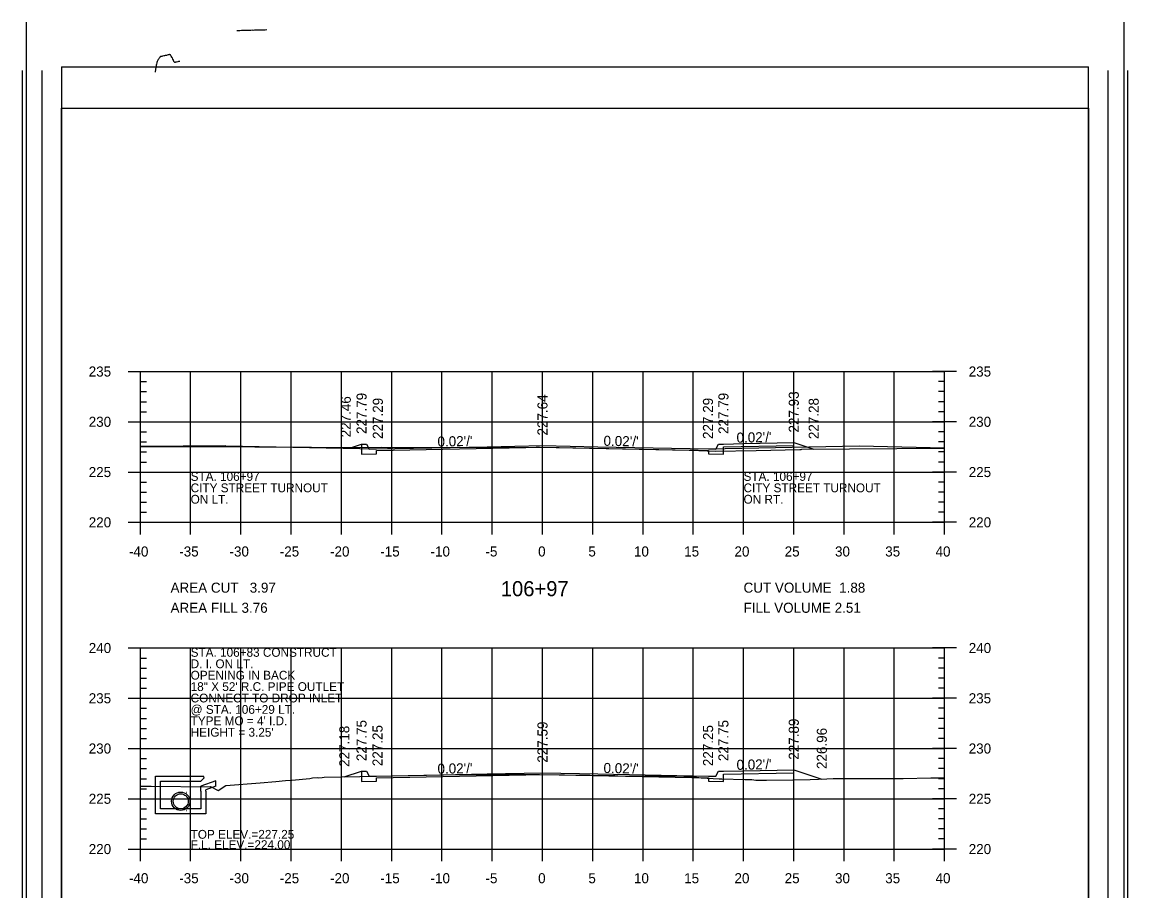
# Model space of a CAD drawing. Extents: x 1367903 to 1373764, y 376865 to 382130.
# Drawn here: x 1371403 to 1371623, y 377447.5 to 377620.4 of the extents above; entities that cross this region are included whole.
import ezdxf

# ---------------------------------------------------------------- set-up
doc = ezdxf.new("R2010")
doc.units = 0
for name, color, linetype in [('R_Axis', 7, 'Continuous'), ('R_Axis Annot', 7, 'Continuous'), ('R_Border', 7, 'Continuous'), ('R_Border PE', 7, 'Continuous'), ('R_Draft', 7, 'Continuous'), ('R_Drive', 7, 'Continuous'), ('R_Exist Surface', 7, 'Continuous'), ('R_Fin Surface', 7, 'Continuous'), ('R_Fin Surface Annot', 7, 'Continuous'), ('R_Grid', 7, 'Continuous'), ('R_Water', 7, 'Continuous'), ('R_Water Annot', 7, 'Continuous')]:
    doc.layers.add(name, color=color, linetype=linetype)

msp = doc.modelspace()

# ---------------------------------------------------------------- linework, layer by layer
for p, q in [((1371429.54, 377470.34), (1371439.04, 377470.34)), ((1371429.54, 377467.34), (1371429.54, 377470.34)), ((1371439.21, 377470), (1371438.54, 377469.34)), ((1371439.21, 377470), (1371439.04, 377470.34)), ((1371430.54, 377467.34), (1371430.54, 377469.34)), ((1371430.54, 377469.34), (1371438.54, 377469.34)), ((1371441.54, 377469.38), (1371438.54, 377468.34)), ((1371438.54, 377467.34), (1371438.54, 377468.34)), ((1371441.54, 377468.32), (1371439.54, 377467.62)), ((1371439.54, 377467.34), (1371439.54, 377467.62))]:
    msp.add_line(p, q)
for points in [[(1371470.51, 377536.42), (1371470.51, 377535.76), (1371470.51, 377535.76), (1371470.51, 377534.39), (1371473.51, 377534.45), (1371473.51, 377535.12), (1371506.51, 377535.78), (1371539.51, 377535.12), (1371539.51, 377534.45), (1371542.51, 377534.39), (1371542.51, 377535.84), (1371556.51, 377536.12), (1371556.51, 377536.7)], [(1371470.51, 377471.33), (1371470.51, 377470.67), (1371470.51, 377470.67), (1371470.51, 377469.3), (1371473.51, 377469.36), (1371473.51, 377470.03), (1371506.51, 377470.69), (1371539.51, 377470.03), (1371539.51, 377469.36), (1371542.51, 377469.3), (1371542.51, 377470.75), (1371556.51, 377471.03), (1371556.51, 377471.61)], [(1371441.54, 377468.32), (1371441.54, 377469.38)]]:
    msp.add_lwpolyline(points)
at = {"layer": 'R_Axis'}
for p, q in [((1371424.11, 377550.84), (1371428.91, 377550.84)), ((1371426.51, 377520.84), (1371426.51, 377550.84)), ((1371588.91, 377550.84), (1371584.11, 377550.84)), ((1371586.51, 377520.84), (1371586.51, 377550.84)), ((1371426.51, 377548.84), (1371427.71, 377548.84)), ((1371586.51, 377548.84), (1371585.31, 377548.84)), ((1371426.51, 377546.84), (1371427.71, 377546.84)), ((1371426.51, 377544.84), (1371427.71, 377544.84)), ((1371586.51, 377546.84), (1371585.31, 377546.84)), ((1371586.51, 377544.84), (1371585.31, 377544.84)), ((1371426.51, 377542.84), (1371427.71, 377542.84)), ((1371586.51, 377542.84), (1371585.31, 377542.84)), ((1371424.11, 377540.84), (1371428.91, 377540.84)), ((1371588.91, 377540.84), (1371584.11, 377540.84)), ((1371426.51, 377538.84), (1371427.71, 377538.84)), ((1371586.51, 377538.84), (1371585.31, 377538.84)), ((1371426.51, 377536.84), (1371427.71, 377536.84)), ((1371586.51, 377536.84), (1371585.31, 377536.84)), ((1371426.51, 377534.84), (1371427.71, 377534.84)), ((1371586.51, 377534.84), (1371585.31, 377534.84)), ((1371426.51, 377532.84), (1371427.71, 377532.84)), ((1371586.51, 377532.84), (1371585.31, 377532.84)), ((1371424.11, 377530.84), (1371428.91, 377530.84)), ((1371588.91, 377530.84), (1371584.11, 377530.84)), ((1371426.51, 377528.84), (1371427.71, 377528.84)), ((1371586.51, 377528.84), (1371585.31, 377528.84)), ((1371426.51, 377526.84), (1371427.71, 377526.84)), ((1371586.51, 377526.84), (1371585.31, 377526.84)), ((1371426.51, 377524.84), (1371427.71, 377524.84)), ((1371426.51, 377518.44), (1371426.51, 377523.24)), ((1371426.51, 377522.84), (1371427.71, 377522.84)), ((1371436.51, 377518.44), (1371436.51, 377523.24)), ((1371446.51, 377518.44), (1371446.51, 377523.24)), ((1371456.51, 377518.44), (1371456.51, 377523.24)), ((1371466.51, 377518.44), (1371466.51, 377523.24)), ((1371476.51, 377518.44), (1371476.51, 377523.24)), ((1371486.51, 377518.44), (1371486.51, 377523.24)), ((1371496.51, 377518.44), (1371496.51, 377523.24)), ((1371506.51, 377518.44), (1371506.51, 377523.24)), ((1371516.51, 377518.44), (1371516.51, 377523.24)), ((1371526.51, 377518.44), (1371526.51, 377523.24)), ((1371536.51, 377518.44), (1371536.51, 377523.24)), ((1371546.51, 377518.44), (1371546.51, 377523.24)), ((1371556.51, 377518.44), (1371556.51, 377523.24)), ((1371566.51, 377518.44), (1371566.51, 377523.24)), ((1371576.51, 377518.44), (1371576.51, 377523.24)), ((1371586.51, 377524.84), (1371585.31, 377524.84)), ((1371586.51, 377522.84), (1371585.31, 377522.84)), ((1371586.51, 377518.44), (1371586.51, 377523.24)), ((1371424.11, 377520.84), (1371428.91, 377520.84)), ((1371426.51, 377520.84), (1371586.51, 377520.84)), ((1371588.91, 377520.84), (1371584.11, 377520.84)), ((1371424.11, 377495.84), (1371428.91, 377495.84)), ((1371426.51, 377455.84), (1371426.51, 377495.84)), ((1371588.91, 377495.84), (1371584.11, 377495.84)), ((1371586.51, 377455.84), (1371586.51, 377495.84)), ((1371426.51, 377493.84), (1371427.71, 377493.84)), ((1371586.51, 377493.84), (1371585.31, 377493.84)), ((1371426.51, 377491.84), (1371427.71, 377491.84)), ((1371426.51, 377489.84), (1371427.71, 377489.84)), ((1371586.51, 377491.84), (1371585.31, 377491.84)), ((1371586.51, 377489.84), (1371585.31, 377489.84)), ((1371426.51, 377487.84), (1371427.71, 377487.84)), ((1371586.51, 377487.84), (1371585.31, 377487.84)), ((1371424.11, 377485.84), (1371428.91, 377485.84)), ((1371588.91, 377485.84), (1371584.11, 377485.84)), ((1371426.51, 377483.84), (1371427.71, 377483.84)), ((1371586.51, 377483.84), (1371585.31, 377483.84)), ((1371426.51, 377481.84), (1371427.71, 377481.84)), ((1371586.51, 377481.84), (1371585.31, 377481.84)), ((1371426.51, 377479.84), (1371427.71, 377479.84)), ((1371586.51, 377479.84), (1371585.31, 377479.84)), ((1371426.51, 377477.84), (1371427.71, 377477.84)), ((1371586.51, 377477.84), (1371585.31, 377477.84)), ((1371424.11, 377475.84), (1371428.91, 377475.84)), ((1371588.91, 377475.84), (1371584.11, 377475.84)), ((1371426.51, 377473.84), (1371427.71, 377473.84)), ((1371586.51, 377473.84), (1371585.31, 377473.84)), ((1371426.51, 377471.84), (1371427.71, 377471.84)), ((1371586.51, 377471.84), (1371585.31, 377471.84)), ((1371426.51, 377469.84), (1371427.71, 377469.84)), ((1371426.51, 377467.84), (1371427.71, 377467.84)), ((1371586.51, 377469.84), (1371585.31, 377469.84)), ((1371586.51, 377467.84), (1371585.31, 377467.84)), ((1371424.11, 377465.84), (1371428.91, 377465.84)), ((1371588.91, 377465.84), (1371584.11, 377465.84)), ((1371426.51, 377463.84), (1371427.71, 377463.84)), ((1371586.51, 377463.84), (1371585.31, 377463.84)), ((1371426.51, 377461.84), (1371427.71, 377461.84)), ((1371586.51, 377461.84), (1371585.31, 377461.84)), ((1371426.51, 377459.84), (1371427.71, 377459.84)), ((1371586.51, 377459.84), (1371585.31, 377459.84)), ((1371426.51, 377453.44), (1371426.51, 377458.24)), ((1371426.51, 377457.84), (1371427.71, 377457.84)), ((1371436.51, 377453.44), (1371436.51, 377458.24)), ((1371446.51, 377453.44), (1371446.51, 377458.24)), ((1371456.51, 377453.44), (1371456.51, 377458.24)), ((1371466.51, 377453.44), (1371466.51, 377458.24)), ((1371476.51, 377453.44), (1371476.51, 377458.24)), ((1371486.51, 377453.44), (1371486.51, 377458.24)), ((1371496.51, 377453.44), (1371496.51, 377458.24)), ((1371506.51, 377453.44), (1371506.51, 377458.24)), ((1371516.51, 377453.44), (1371516.51, 377458.24)), ((1371526.51, 377453.44), (1371526.51, 377458.24)), ((1371536.51, 377453.44), (1371536.51, 377458.24)), ((1371546.51, 377453.44), (1371546.51, 377458.24)), ((1371556.51, 377453.44), (1371556.51, 377458.24)), ((1371566.51, 377453.44), (1371566.51, 377458.24)), ((1371576.51, 377453.44), (1371576.51, 377458.24)), ((1371586.51, 377457.84), (1371585.31, 377457.84)), ((1371586.51, 377453.44), (1371586.51, 377458.24)), ((1371424.11, 377455.84), (1371428.91, 377455.84)), ((1371426.51, 377455.84), (1371586.51, 377455.84)), ((1371588.91, 377455.84), (1371584.11, 377455.84))]:
    msp.add_line(p, q, dxfattribs=at)
at = {"layer": 'R_Border'}
for p, q in [((1371403.79, 377620.35), (1371403.79, 377279.12)), ((1371622.18, 377620.35), (1371622.18, 377279.12)), ((1371410.82, 377611.47), (1371615.14, 377611.47)), ((1371410.82, 377611.47), (1371410.82, 377280.59)), ((1371615.14, 377280.59), (1371615.14, 377611.47))]:
    msp.add_line(p, q, dxfattribs=at)
at = {"layer": 'R_Border PE'}
for p, q in [((1371402.98, 377610.76), (1371402.98, 377288.8)), ((1371406.9, 377610.76), (1371406.9, 377288.8)), ((1371619.06, 377288.8), (1371619.06, 377610.76)), ((1371622.98, 377288.8), (1371622.98, 377610.76)), ((1371410.82, 377603.25), (1371615.14, 377603.25)), ((1371410.82, 377288.8), (1371410.82, 377603.25)), ((1371615.14, 377603.25), (1371615.14, 377288.8))]:
    msp.add_line(p, q, dxfattribs=at)
for points in [[(1371447.67, 377618.69), (1371447.62, 377618.69), (1371447.34, 377618.68), (1371447.21, 377618.68), (1371447.14, 377618.67), (1371446.99, 377618.67), (1371446.63, 377618.66), (1371446.3, 377618.65), (1371445.67, 377618.63)], [(1371448.13, 377618.7), (1371447.67, 377618.69)], [(1371451.69, 377618.79), (1371451.34, 377618.78), (1371451.14, 377618.78), (1371450.98, 377618.77), (1371450.75, 377618.76), (1371450.6, 377618.76), (1371450.4, 377618.75), (1371450.15, 377618.75), (1371449.96, 377618.74), (1371449.68, 377618.73), (1371449.58, 377618.73), (1371449.53, 377618.73), (1371449.31, 377618.72), (1371449.21, 377618.72), (1371448.98, 377618.71), (1371448.9, 377618.72), (1371448.48, 377618.7), (1371448.24, 377618.7), (1371448.13, 377618.7)], [(1371434.37, 377612.54), (1371434.35, 377612.55), (1371434.33, 377612.55), (1371434.31, 377612.55), (1371434.29, 377612.55), (1371434.26, 377612.55), (1371434.24, 377612.55), (1371434.21, 377612.55), (1371434.07, 377612.51), (1371433.95, 377612.48), (1371433.68, 377612.41), (1371433.47, 377612.36), (1371433.44, 377612.35), (1371433.42, 377612.35), (1371433.4, 377612.34), (1371433.39, 377612.34), (1371433.38, 377612.35), (1371433.35, 377612.35), (1371433.33, 377612.36), (1371433.31, 377612.38), (1371433.29, 377612.39), (1371433.27, 377612.4), (1371433.25, 377612.42), (1371433.23, 377612.45), (1371433.22, 377612.47), (1371433.2, 377612.5), (1371433.18, 377612.55), (1371433.09, 377612.76), (1371432.98, 377613), (1371432.87, 377613.23), (1371432.86, 377613.26), (1371432.85, 377613.28), (1371432.81, 377613.34), (1371432.78, 377613.39), (1371432.66, 377613.57), (1371432.58, 377613.69), (1371432.55, 377613.74), (1371432.54, 377613.76), (1371432.52, 377613.78), (1371432.5, 377613.81), (1371432.48, 377613.83), (1371432.47, 377613.84), (1371432.45, 377613.85), (1371432.42, 377613.87), (1371432.41, 377613.87), (1371432.38, 377613.88), (1371432.35, 377613.88), (1371432.34, 377613.88), (1371432.3, 377613.88), (1371432.2, 377613.86), (1371432.03, 377613.82), (1371431.83, 377613.77), (1371431.69, 377613.74), (1371431.58, 377613.72), (1371431.44, 377613.69), (1371431.32, 377613.66), (1371431.15, 377613.63), (1371430.93, 377613.58), (1371430.88, 377613.57), (1371430.76, 377613.54), (1371430.64, 377613.52), (1371430.6, 377613.51), (1371430.57, 377613.5), (1371430.55, 377613.5), (1371430.54, 377613.49), (1371430.52, 377613.49), (1371430.5, 377613.47), (1371430.48, 377613.46), (1371430.46, 377613.44), (1371430.44, 377613.42), (1371430.41, 377613.39), (1371430.38, 377613.35), (1371430.35, 377613.31), (1371430.31, 377613.26), (1371430.25, 377613.16), (1371430.16, 377613.02), (1371430.08, 377612.89), (1371429.98, 377612.75), (1371429.93, 377612.67), (1371429.89, 377612.62), (1371429.86, 377612.55), (1371429.85, 377612.54), (1371429.84, 377612.52), (1371429.83, 377612.5), (1371429.82, 377612.48), (1371429.82, 377612.46), (1371429.81, 377612.44), (1371429.8, 377612.42), (1371429.8, 377612.39), (1371429.79, 377612.37), (1371429.79, 377612.35), (1371429.78, 377612.33), (1371429.77, 377612.24), (1371429.73, 377612), (1371429.68, 377611.76), (1371429.66, 377611.65), (1371429.58, 377611.18), (1371429.55, 377611.04), (1371429.51, 377610.84), (1371429.46, 377610.54), (1371429.43, 377610.39)]]:
    msp.add_lwpolyline(points, dxfattribs=at)
at = {"layer": 'R_Drive'}
for p, q in [((1371443.52, 377536.05), (1371426.51, 377535.91)), ((1371443.52, 377536.05), (1371473.51, 377535.45)), ((1371539.51, 377535.45), (1371569.51, 377536.05)), ((1371569.51, 377536.05), (1371586.51, 377535.63))]:
    msp.add_line(p, q, dxfattribs=at)
at = {"layer": 'R_Exist Surface'}
for points in [[(1371426.51, 377535.93), (1371433.1, 377535.94), (1371437.5, 377535.94), (1371437.96, 377535.95), (1371471.9, 377535.73), (1371474.41, 377535.76), (1371475.66, 377535.72), (1371475.7, 377535.71), (1371475.73, 377535.71), (1371476.68, 377535.73), (1371505.26, 377535.79), (1371505.54, 377535.79), (1371505.6, 377535.79), (1371505.94, 377535.78), (1371535.7, 377535.19), (1371537.44, 377535.18), (1371537.6, 377535.15), (1371540.85, 377534.98), (1371549, 377535.15), (1371557.7, 377535.36), (1371557.97, 377535.36), (1371558.14, 377535.37), (1371586.51, 377535.56)], [(1371426.51, 377468.34), (1371428.64, 377468.32), (1371440.39, 377468.24), (1371440.49, 377468.25), (1371441.98, 377467.51), (1371441.98, 377467.51), (1371443.48, 377468.47), (1371450.34, 377469.01), (1371453.45, 377469.3), (1371455.36, 377469.46), (1371456.64, 377469.53), (1371460.2, 377469.9), (1371460.73, 377470.02), (1371461.76, 377470.05), (1371462.01, 377470.01), (1371462.68, 377470.09), (1371463.08, 377470.11), (1371470.2, 377470.26), (1371472.92, 377470.32), (1371476.43, 377470.4), (1371476.7, 377470.4), (1371490.23, 377470.68), (1371490.42, 377470.68), (1371503.39, 377470.69), (1371503.98, 377470.68), (1371505.92, 377470.65), (1371505.93, 377470.65), (1371520.9, 377470.44), (1371521.52, 377470.43), (1371534.62, 377470.32), (1371536.23, 377470.27), (1371538.06, 377469.99), (1371541.65, 377469.84), (1371542.18, 377469.82), (1371546.79, 377469.68), (1371548.17, 377469.68), (1371548.96, 377469.56), (1371549.29, 377469.54), (1371551.09, 377469.57), (1371556.3, 377469.62), (1371559.76, 377469.65), (1371563.06, 377469.8), (1371564.34, 377469.88), (1371570.17, 377469.86), (1371578.25, 377469.89), (1371583.8, 377469.98), (1371586.51, 377470.01)]]:
    msp.add_lwpolyline(points, dxfattribs=at)
at = {"layer": 'R_Fin Surface'}
for points in [[(1371468.5, 377535.75), (1371470.51, 377536.42), (1371471.51, 377536.42), (1371472.01, 377535.42), (1371473.51, 377535.45), (1371495.51, 377535.89), (1371506.51, 377536.11), (1371517.51, 377535.89), (1371539.51, 377535.45), (1371541.01, 377535.42), (1371541.51, 377536.42), (1371542.51, 377536.42), (1371546.51, 377536.5), (1371556.51, 377536.7), (1371560.47, 377535.39)], [(1371467.08, 377470.19), (1371470.51, 377471.33), (1371471.51, 377471.33), (1371472.01, 377470.33), (1371473.51, 377470.36), (1371495.51, 377470.8), (1371506.51, 377471.02), (1371517.51, 377470.8), (1371539.51, 377470.36), (1371541.01, 377470.33), (1371541.51, 377471.33), (1371542.51, 377471.33), (1371546.51, 377471.41), (1371556.51, 377471.61), (1371562.08, 377469.76)]]:
    msp.add_lwpolyline(points, dxfattribs=at)
at = {"layer": 'R_Grid'}
for p, q in [((1371426.51, 377550.84), (1371586.51, 377550.84)), ((1371426.51, 377520.84), (1371426.51, 377550.84)), ((1371436.51, 377520.84), (1371436.51, 377550.84)), ((1371446.51, 377520.84), (1371446.51, 377550.84)), ((1371456.51, 377520.84), (1371456.51, 377550.84)), ((1371466.51, 377520.84), (1371466.51, 377550.84)), ((1371476.51, 377520.84), (1371476.51, 377550.84)), ((1371486.51, 377520.84), (1371486.51, 377550.84)), ((1371496.51, 377520.84), (1371496.51, 377550.84)), ((1371506.51, 377520.84), (1371506.51, 377550.84)), ((1371516.51, 377520.84), (1371516.51, 377550.84)), ((1371526.51, 377520.84), (1371526.51, 377550.84)), ((1371536.51, 377520.84), (1371536.51, 377550.84)), ((1371546.51, 377520.84), (1371546.51, 377550.84)), ((1371556.51, 377520.84), (1371556.51, 377550.84)), ((1371566.51, 377520.84), (1371566.51, 377550.84)), ((1371576.51, 377520.84), (1371576.51, 377550.84)), ((1371586.51, 377520.84), (1371586.51, 377550.84)), ((1371426.51, 377540.84), (1371586.51, 377540.84)), ((1371426.51, 377530.84), (1371586.51, 377530.84)), ((1371426.51, 377520.84), (1371586.51, 377520.84)), ((1371426.51, 377495.84), (1371586.51, 377495.84)), ((1371426.51, 377455.84), (1371426.51, 377495.84)), ((1371436.51, 377455.84), (1371436.51, 377495.84)), ((1371446.51, 377455.84), (1371446.51, 377495.84)), ((1371456.51, 377455.84), (1371456.51, 377495.84)), ((1371466.51, 377455.84), (1371466.51, 377495.84)), ((1371476.51, 377455.84), (1371476.51, 377495.84)), ((1371486.51, 377455.84), (1371486.51, 377495.84)), ((1371496.51, 377455.84), (1371496.51, 377495.84)), ((1371506.51, 377455.84), (1371506.51, 377495.84)), ((1371516.51, 377455.84), (1371516.51, 377495.84)), ((1371526.51, 377455.84), (1371526.51, 377495.84)), ((1371536.51, 377455.84), (1371536.51, 377495.84)), ((1371546.51, 377455.84), (1371546.51, 377495.84)), ((1371556.51, 377455.84), (1371556.51, 377495.84)), ((1371566.51, 377455.84), (1371566.51, 377495.84)), ((1371576.51, 377455.84), (1371576.51, 377495.84)), ((1371586.51, 377455.84), (1371586.51, 377495.84)), ((1371426.51, 377485.84), (1371586.51, 377485.84)), ((1371426.51, 377475.84), (1371586.51, 377475.84)), ((1371426.51, 377465.84), (1371586.51, 377465.84)), ((1371426.51, 377455.84), (1371586.51, 377455.84))]:
    msp.add_line(p, q, dxfattribs=at)
at = {"layer": 'R_Water'}
for p, q in [((1371435.69, 377467.18), (1371435.73, 377467.18)), ((1371435.69, 377466.84), (1371435.73, 377466.84)), ((1371435.69, 377463.84), (1371435.73, 377463.84)), ((1371435.69, 377463.51), (1371435.73, 377463.51))]:
    msp.add_line(p, q, dxfattribs=at)
for points in [[(1371439.54, 377467.34), (1371439.54, 377462.84), (1371434.54, 377462.84), (1371429.54, 377462.84), (1371429.54, 377467.34)], [(1371438.54, 377467.34), (1371438.54, 377463.84), (1371434.54, 377463.84), (1371430.54, 377463.84), (1371430.54, 377467.34)]]:
    msp.add_lwpolyline(points, dxfattribs=at)
for radius in [1.83, 1.5]:
    msp.add_circle((1371434.54, 377465.34), radius, dxfattribs=at)

# ---------------------------------------------------------------- texts
at = {"layer": 'R_Axis Annot'}
for s, height, p in [('235', 2, (1371416.23, 377549.84)), ('235', 2, (1371591.31, 377549.84)), ('230', 2, (1371416.23, 377539.84)), ('230', 2, (1371591.31, 377539.84)), ('225', 2, (1371416.23, 377529.84)), ('225', 2, (1371591.31, 377529.84)), ('220', 2, (1371416.23, 377519.84)), ('220', 2, (1371591.31, 377519.84)), ('-40', 2, (1371424.24, 377514.04)), ('-35', 2, (1371434.24, 377514.04)), ('-30', 2, (1371444.24, 377514.04)), ('-25', 2, (1371454.24, 377514.04)), ('-20', 2, (1371464.24, 377514.04)), ('-15', 2, (1371474.24, 377514.04)), ('-10', 2, (1371484.24, 377514.04)), ('-5', 2, (1371495.17, 377514.04)), ('0', 2, (1371505.64, 377514.04)), ('5', 2, (1371515.64, 377514.04)), ('10', 2, (1371524.71, 377514.04)), ('15', 2, (1371534.7, 377514.04)), ('20', 2, (1371544.71, 377514.04)), ('25', 2, (1371554.7, 377514.04)), ('30', 2, (1371564.71, 377514.04)), ('35', 2, (1371574.7, 377514.04)), ('40', 2, (1371584.71, 377514.04)), ('AREA CUT   3.97', 2, (1371432.51, 377506.84)), ('106+97', 3, (1371498.22, 377506.14)), ('CUT VOLUME  1.88', 2, (1371546.51, 377506.84)), ('AREA FILL 3.76', 2, (1371432.51, 377502.84)), ('FILL VOLUME 2.51', 2, (1371546.51, 377502.84)), ('240', 2, (1371416.23, 377494.84)), ('240', 2, (1371591.31, 377494.84)), ('235', 2, (1371416.23, 377484.84)), ('235', 2, (1371591.31, 377484.84)), ('230', 2, (1371416.23, 377474.84)), ('230', 2, (1371591.31, 377474.84)), ('225', 2, (1371416.23, 377464.84)), ('225', 2, (1371591.31, 377464.84)), ('220', 2, (1371416.23, 377454.84)), ('220', 2, (1371591.31, 377454.84)), ('-40', 2, (1371424.24, 377449.04)), ('-35', 2, (1371434.24, 377449.04)), ('-30', 2, (1371444.24, 377449.04)), ('-25', 2, (1371454.24, 377449.04)), ('-20', 2, (1371464.24, 377449.04)), ('-15', 2, (1371474.24, 377449.04)), ('-10', 2, (1371484.24, 377449.04)), ('-5', 2, (1371495.17, 377449.04)), ('0', 2, (1371505.64, 377449.04)), ('5', 2, (1371515.64, 377449.04)), ('10', 2, (1371524.71, 377449.04)), ('15', 2, (1371534.7, 377449.04)), ('20', 2, (1371544.71, 377449.04)), ('25', 2, (1371554.7, 377449.04)), ('30', 2, (1371564.71, 377449.04)), ('35', 2, (1371574.7, 377449.04)), ('40', 2, (1371584.71, 377449.04))]:
    msp.add_text(s, height=height, dxfattribs=at).set_placement(p)
at = {"layer": 'R_Draft'}
for s, p in [('STA. 106+97', (1371436.51, 377529.09)), ('STA. 106+97', (1371546.51, 377529.09)), ('CITY STREET TURNOUT', (1371436.51, 377526.82)), ('CITY STREET TURNOUT', (1371546.51, 377526.82)), ('ON LT.', (1371436.51, 377524.55)), ('ON RT.', (1371546.51, 377524.55)), ('STA. 106+83 CONSTRUCT', (1371436.51, 377494.09)), ('D. I. ON LT.', (1371436.51, 377491.82)), ('OPENING IN BACK', (1371436.51, 377489.55)), ('18" X 52\' R.C. PIPE OUTLET', (1371436.51, 377487.28)), ('CONNECT TO DROP INLET', (1371436.51, 377485.01)), ('@ STA. 106+29 LT.', (1371436.51, 377482.74)), ("TYPE MO = 4' I.D.", (1371436.51, 377480.47)), ("HEIGHT = 3.25'", (1371436.51, 377478.2))]:
    msp.add_text(s, height=1.75, dxfattribs=at).set_placement(p)
at = {"layer": 'R_Fin Surface Annot'}
for s, rotation, p in [('227.46', 90, (1371468.38, 377537.75)), ('227.79', 90, (1371471.51, 377538.42)), ('227.29', 90, (1371474.75, 377537.42)), ('227.64', 90, (1371507.51, 377538.11)), ('227.29', 90, (1371540.43, 377537.42)), ('227.79', 90, (1371543.51, 377538.42)), ('227.93', 90, (1371557.51, 377538.7)), ('227.28', 90, (1371561.47, 377537.39)), ("0.02'/'", 1.1457, (1371545.14, 377536.68)), ("0.02'/'", 1.1457, (1371485.64, 377535.9)), ("0.02'/'", 358.8542, (1371518.64, 377536.07)), ('227.75', 90, (1371471.51, 377473.33)), ('227.59', 90, (1371507.51, 377473.02)), ('227.75', 90, (1371543.51, 377473.33)), ('227.89', 90, (1371557.51, 377473.61)), ('227.18', 90, (1371468.08, 377472.19)), ('227.25', 90, (1371474.69, 377472.33)), ('227.25', 90, (1371540.46, 377472.33)), ('226.96', 90, (1371563.08, 377471.76)), ("0.02'/'", 1.1455, (1371485.64, 377470.81)), ("0.02'/'", 358.854, (1371518.64, 377470.98)), ("0.02'/'", 1.1455, (1371545.14, 377471.59))]:
    msp.add_text(s, height=2, rotation=rotation, dxfattribs=at).set_placement(p)
at = {"layer": 'R_Water Annot'}
for s, p in [('TOP ELEV.=227.25', (1371436.51, 377457.89)), ('F.L. ELEV.=224.00', (1371436.51, 377455.84))]:
    msp.add_text(s, height=1.75, dxfattribs=at).set_placement(p)

doc.saveas('drawing.dxf')
